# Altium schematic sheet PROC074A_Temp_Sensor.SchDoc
size 431 x 279 mm; Date: Not shown in title block; ApprovedBy: Not shown in title block; CheckedBy: Not shown in title block; Author: Not shown in title block; CompanyName: Not shown in title block; Engineer: Not shown in title block; Organization: Not shown in title block; Address1: Not shown in title block; Address2: Not shown in title block; Address3: Not shown in title block; Address4: Not shown in title block; DocumentNumber: 1; Revision: Use project parameter SCH_Rev; SheetNumber: 15; SheetTotal: 22; PageSetup: Record=PageOptions¦CenterHorizontal=True¦CenterVertical=True¦PrintScale=1.00¦XCorrection=1.00¦YCorrection=1.00¦PrintKind=0¦BorderSize=5000000¦LeftOffset=0¦BottomOffset=0¦Orientation=2¦PaperLength=1000¦PaperWidth=1000¦Scale=100¦PaperSource=15¦PrintQuality=600¦MediaType=1¦DitherType=10¦PaperKind=Letter¦PrintScaleMode=1
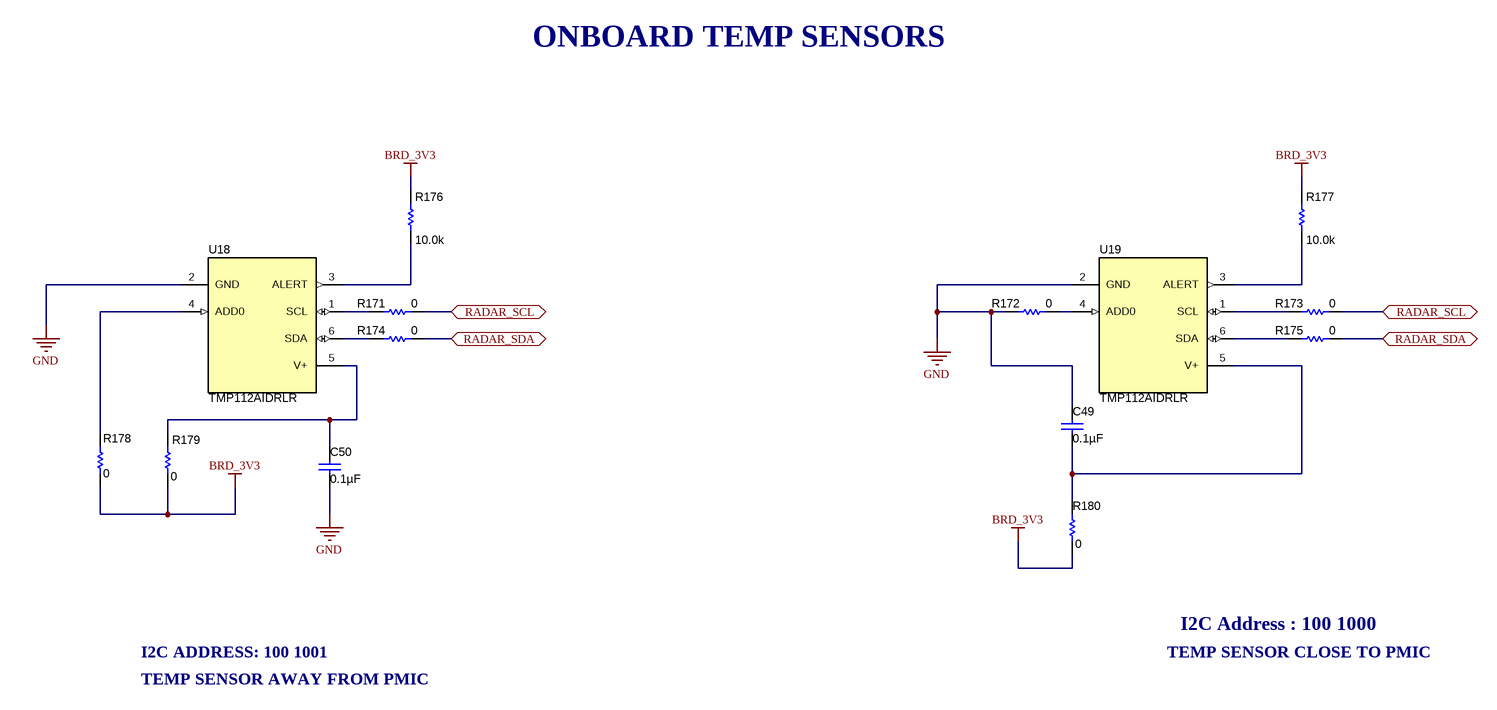
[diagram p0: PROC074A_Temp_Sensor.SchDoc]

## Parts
C49  ValueDisplayed: 0.1µF  [0402L]  (hidden comment: C0402C104K8RACTU)
C50  ValueDisplayed: 0.1µF  [0402L]  (hidden comment: C0402C104K8RACTU)
R171  ValueDisplayed: 0  [0201_Silk]  (hidden comment: CRCW02010000Z0ED)
R172  ValueDisplayed: 0  [0201_Silk]  (hidden comment: CRCW02010000Z0ED)
R173  ValueDisplayed: 0  [0201_Silk]  (hidden comment: CRCW02010000Z0ED)
R174  ValueDisplayed: 0  [0201_Silk]  (hidden comment: CRCW02010000Z0ED)
R175  ValueDisplayed: 0  [0201_Silk]  (hidden comment: CRCW02010000Z0ED)
R176  ValueDisplayed: 10.0k  [0402L]  (hidden comment: CRCW040210K0FKED)
R177  ValueDisplayed: 10.0k  [0402L]  (hidden comment: CRCW040210K0FKED)
R178  ValueDisplayed: 0  [0201_Silk]  (hidden comment: CRCW02010000Z0ED)
R179  ValueDisplayed: 0  [0402L]  (hidden comment: ERJ-2GE0R00X)
R180  ValueDisplayed: 0  [0402L]  (hidden comment: ERJ-2GE0R00X)
U18  TMP112AIDRLR  [DRL0006A]
U19  TMP112AIDRLR  [DRL0006A]

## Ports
RADAR_SCL, RADAR_SDA

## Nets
BRD_3V3: R176.1 R177.1 R178.2 R179.2 R180.2
GND: C49.1 C50.2 R172.1 U18.2(GND) U19.2(GND)
RADAR_SCL: R171.1 R173.1 ; port RADAR_SCL
RADAR_SDA: R174.2 R175.2 ; port RADAR_SDA
NetC49_2: C49.2 R180.1 U19.5(V+)
NetC50_1: C50.1 R179.1 U18.5(V+)
NetR171_2: R171.2 U18.1(SCL)
NetR172_2: R172.2 U19.4(ADD0)
NetR173_2: R173.2 U19.1(SCL)
NetR174_1: R174.1 U18.6(SDA)
NetR175_1: R175.1 U19.6(SDA)
NetR176_2: R176.2 U18.3(ALERT)
NetR177_2: R177.2 U19.3(ALERT)
NetR178_1: R178.1 U18.4(ADD0)

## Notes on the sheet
- ONBOARD TEMP SENSORS
- I2C ADDRESS: 100 1001
- TEMP SENSOR CLOSE TO PMIC
- I2C Address : 100 1000
- TEMP SENSOR AWAY FROM PMIC

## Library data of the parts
C49 C50 = CMP-0078241-1: CAP, CERM, 0.1 µF, 10 V,+/- 10%, X7R, 0402; Manufacturer: Kemet; TaMin_C: -55°C; Polarized: N; SizeAreaWB_mm2: 3; U/M: EA; Value: 0.1uF; TaMax_C: 125°C; SizeZ_mm: 0.6; SizeX_mm: 1; SizeY_mm: 0.5; Cap_Case: 0402; Value2: 10V; CompType: Capacitor; Cap_F: 100nF; AEC Category: Q200
R171-R175 R178 = CMP-0027008-3: RES, 0, 5%, 0.05 W, 0201; Manufacturer: Vishay-Dale; Power_W: 50mW; TempCo: ppm/C; Value_Code: 0000; U/M: EA; Value: 0; EIA_Code: E24; SizeX_mm: 0.6; SizeY_mm: 0.3; SizeZ_mm: 0.26; Value2: 0.05W; SizeArea_mm2: 0.18; AEC Qualified: N; AEC Category: Q200
R176 R177 = CMP-0025958-2: RES, 10.0 k, 1%, 0.063 W, 0402; Manufacturer: Vishay-Dale; Power_W: 63mW; TempCo: 100 ppm/C; Value_Code: 10k0; U/M: EA; Value: 10.0k; EIA_Code: E96; Res_ohm: 10k; SizeX_mm: 1; SizeY_mm: 0.5; SizeZ_mm: 0.6; Value2: 0.063W; VDC_V: 50V; AEC Category: Q200
R179 R180 = CMP-0026992-2: RES, 0, 5%, 0.063 W, 0402; Manufacturer: Panasonic; Power_W: 63mW; TempCo: 600 ppm/C; Value_Code: 0000; U/M: EA; Value: 0; EIA_Code: E24; SizeX_mm: 1; SizeY_mm: 0.5; SizeZ_mm: 0.6; Value2: 0.063W; VDC_V: 50V; AEC Category: Q200
U18 U19 = CMP-0067397-2: 1.4V-Capable +/-0.5degC Temperature Sensor with Alert Function and I2C/SMBus interface in SOT-563, DRL0006A (SOT-OTHER-6); Alternate PartNumber: TMP112AIDRLT; Alternate Manufacturer: Texas Instruments; Green_Lifecycle: Active; SizeAreaWB_mm2: 6.76; Green_REACh: Passed; U/M: EA; SizeZ_mm: 0.6; SizeX_mm: 1.6; SizeArea_mm2: 2.56; CompType: IC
